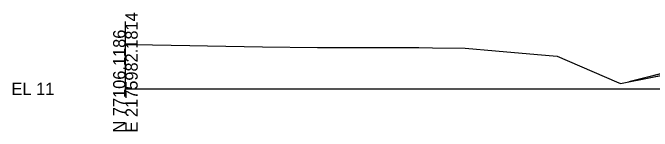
# Model space of a CAD drawing. Extents: x 2177029 to 2201446, y 59897 to 78390.
# Drawn here: x 2199017 to 2199162.9, y 66897.6 to 66924.7 of the extents above; entities that cross this region are included whole.
import ezdxf

# ---------------------------------------------------------------- set-up
doc = ezdxf.new("R2010")
doc.units = 0
for name, color, linetype in [('Exist Cross Section Cell', 7, 'Continuous'), ('Exist XS Ground Line', 7, 'Continuous'), ('Old_Level_3', 7, 'Continuous'), ('Prop CMT Top Wall Envelope', 7, 'Continuous'), ('Prop Hatching', 7, 'Continuous'), ('Prop XS Side Slope Text', 7, 'Continuous')]:
    doc.layers.add(name, color=color, linetype=linetype)

msp = doc.modelspace()

# ---------------------------------------------------------------- linework, layer by layer
at = {"layer": 'Exist Cross Section Cell'}
msp.add_line((2199042.73, 66907.31), (2199242.73, 66907.31), dxfattribs=at)
at = {"layer": 'Exist XS Ground Line'}
msp.add_lwpolyline([(2199042.73, 66917.42), (2199048.94, 66917.33), (2199057.41, 66917.21), (2199061.47, 66917.14), (2199074.04, 66916.88), (2199086.54, 66916.76), (2199090.57, 66916.74), (2199099.07, 66916.77), (2199107.16, 66916.75), (2199109.69, 66916.72), (2199112.79, 66916.69), (2199120.21, 66916.59), (2199127.14, 66915.96), (2199136.73, 66915.13), (2199141.2, 66914.78), (2199154.77, 66908.94), (2199155.68, 66908.54), (2199156.82, 66908.75), (2199175.77, 66912.52)], dxfattribs=at)
at = {"layer": 'Old_Level_3'}
msp.add_line((2199042.73, 66905.94), (2199042.73, 66922.68), dxfattribs=at)
at = {"layer": 'Prop Hatching'}
msp.add_line((2199173.72, 66912.94), (2199157.57, 66908.9), dxfattribs=at)
at = {"layer": 'Prop XS Side Slope Text'}
msp.add_lwpolyline([(2199157.57, 66908.9), (2199172.45, 66911.86), (2199168.46, 66911.62)], close=True, dxfattribs=at)

# ---------------------------------------------------------------- texts
at = {"layer": 'Exist Cross Section Cell'}
for s, p in [('E 2175982.1814', (2199045.53, 66897.31)), ('N 77106.1186', (2199042.73, 66897.31))]:
    msp.add_text(s, height=2.8, rotation=90, dxfattribs=at).set_placement(p)
msp.add_text('EL 11', height=2.8, dxfattribs=at).set_placement((2199016.73, 66905.91))
at = {"layer": 'Prop CMT Top Wall Envelope'}
msp.add_text('-', height=0.0001, dxfattribs=at).set_placement((2199042.73, 66907.31))
msp.add_text('-', height=0.0001, dxfattribs=at).set_placement((2199042.73, 66907.31))

doc.saveas('drawing.dxf')
